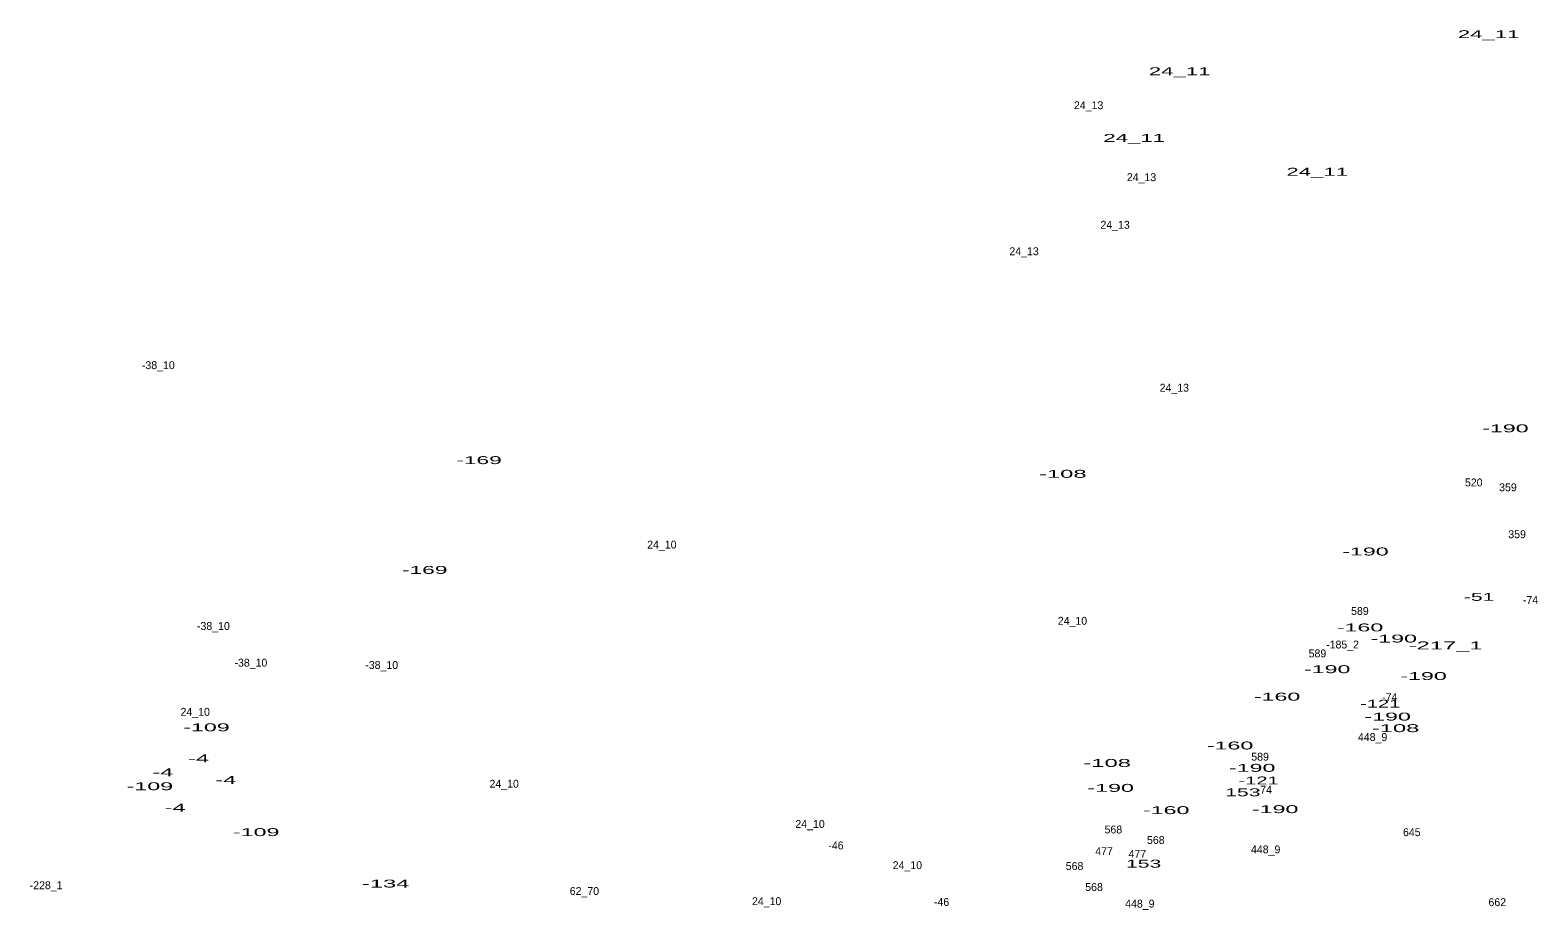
# Model space of a CAD drawing. Extents: x -661742 to -657295, y -1002932 to -996888.
# Drawn here: x -661197 to -660433, y -1001403 to -1000957 of the extents above; entities that cross this region are included whole.
import ezdxf
from ezdxf.enums import TextEntityAlignment as Align

# ---------------------------------------------------------------- set-up
doc = ezdxf.new("R2010")
doc.units = 0
doc.header["$LTSCALE"] = 1.6
doc.layers.add('24', color=7, linetype='Continuous')

msp = doc.modelspace()

# ---------------------------------------------------------------- texts
at = {"layer": '24'}
for s, width, p in [('24_11', 2.1, (-660457.941, -1000960.83)), ('24_11', 2.1, (-660614.551, -1000979.61)), ('24_11', 2.1, (-660637.621, -1001013.41)), ('24_11', 2.1, (-660544.831, -1001030.58)), ('-190', 2.2, (-660449.451, -1001160.7)), ('-169', 2.15, (-660969.679, -1001176.82)), ('-108', 2.25, (-660673.777, -1001183.76)), ('-190', 2.2, (-660520.411, -1001223.15)), ('-169', 2.15, (-660997.209, -1001232.48)), ('-51', 2, (-660462.761, -1001246.16)), ('-160', 2.2, (-660523.131, -1001261.65)), ('-190', 2.2, (-660506.061, -1001267.3)), ('-217_1', 2.25, (-660479.743, -1001270.77)), ('-190', 2.2, (-660539.791, -1001282.82)), ('-190', 2.2, (-660490.941, -1001286.31)), ('-160', 2.2, (-660565.201, -1001296.76)), ('-121', 1.9, (-660512.887, -1001300.27)), ('-190', 2.2, (-660509.161, -1001306.87)), ('-109', 2.2, (-661107.831, -1001312.31)), ('-108', 2.25, (-660505.117, -1001312.73)), ('-160', 2.2, (-660589.011, -1001321.52)), ('-4', 2.25, (-661111.84, -1001328.08)), ('-108', 2.25, (-660651.287, -1001330.38)), ('-190', 2.2, (-660577.791, -1001332.86)), ('-109', 2.2, (-661136.531, -1001342.18)), ('-4', 2.25, (-661129.92, -1001335.11)), ('-4', 2.25, (-661098.07, -1001338.99)), ('-121', 1.9, (-660574.537, -1001339.25)), ('-190', 2.2, (-660649.521, -1001343.01)), ('153', 2, (-660582.527, -1001345.26)), ('-4', 2.25, (-661123.76, -1001353.1)), ('-160', 2.2, (-660621.381, -1001354.3)), ('-190', 2.2, (-660566.161, -1001353.8)), ('-109', 2.2, (-661082.631, -1001365.45)), ('153', 2, (-660632.807, -1001381.44)), ('-134', 2.25, (-661017.016, -1001391.53))]:
    msp.add_text(s, height=4, dxfattribs=dict(at, width=width)).set_placement(p, align=Align.CENTER)
for s, p in [('24_13', (-660660.703, -1000996.84)), ('24_13', (-660633.883, -1001033.33)), ('24_13', (-660647.293, -1001057.48)), ('24_13', (-660693.423, -1001070.89)), ('-38_10', (-661132.24, -1001128.66)), ('24_13', (-660617.263, -1001140.11)), ('520', (-660465.481, -1001188.12)), ('359', (-660448.163, -1001190.59)), ('24_10', (-660876.997, -1001219.64)), ('359', (-660443.523, -1001214.39)), ('-74', (-660436.715, -1001247.73)), ('24_10', (-660668.897, -1001258.28)), ('589', (-660523.203, -1001253.31)), ('-38_10', (-661104.32, -1001260.93)), ('-185_2', (-660531.986, -1001270.32)), ('-38_10', (-661085.32, -1001279.54)), ('-38_10', (-661019.02, -1001280.71)), ('589', (-660544.723, -1001274.83)), ('-74', (-660508.055, -1001296.99)), ('24_10', (-661113.537, -1001304.45)), ('448_9', (-660516.759, -1001317.24)), ('589', (-660573.803, -1001327.2)), ('24_10', (-660956.917, -1001340.91)), ('-74', (-660571.645, -1001343.93)), ('24_10', (-660801.907, -1001361.3)), ('568', (-660648.163, -1001364.12)), ('645', (-660496.887, -1001365.48)), ('-46', (-660788.745, -1001372.18)), ('568', (-660626.643, -1001369.45)), ('477', (-660652.873, -1001375.12)), ('477', (-660636.013, -1001376.48)), ('448_9', (-660570.959, -1001374.18)), ('24_10', (-660752.567, -1001382.22)), ('568', (-660667.833, -1001382.64)), ('-228_1', (-661189.116, -1001392.38)), ('62_70', (-660916.26, -1001395.31)), ('568', (-660657.953, -1001393.3)), ('24_10', (-660823.897, -1001400.46)), ('-46', (-660735.235, -1001400.88)), ('448_9', (-660634.739, -1001401.71)), ('662', (-660453.558, -1001400.97))]:
    msp.add_text(s, height=4, dxfattribs=at).set_placement(p, align=Align.CENTER)

doc.saveas('drawing.dxf')
